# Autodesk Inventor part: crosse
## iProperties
Shininess: 31.0
Length Units: 11269
Angle Units: 11279
Time Units: 11290
Mass Units: 11283
Length Display Precision: 3
Angle Display Precision: 2
Compacted: True
Created: 2002-07
Part Number: crosse
Material: Acier doux
Document SubType Name: Modélisation
Designer: robert
Density: 7.86 g/cm^3
Density: 0.0
Volumn: 0.0
Area: 0.0
PropertySet Name: Model Information
Control State: 0
Master: False
Checked Out: False
Author: robert
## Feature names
1. Extrusion1
2. Extrusion2
3. Révolution1 [Revolution]
4. Révolution2 [Revolution]
5. Extrusion3
6. Extrusion4
7. Perçage1 [Hole]
